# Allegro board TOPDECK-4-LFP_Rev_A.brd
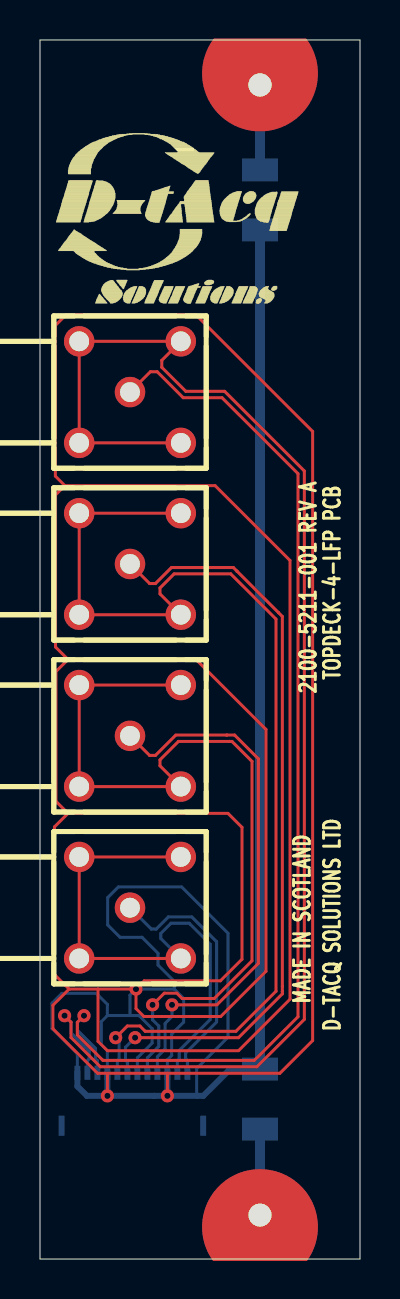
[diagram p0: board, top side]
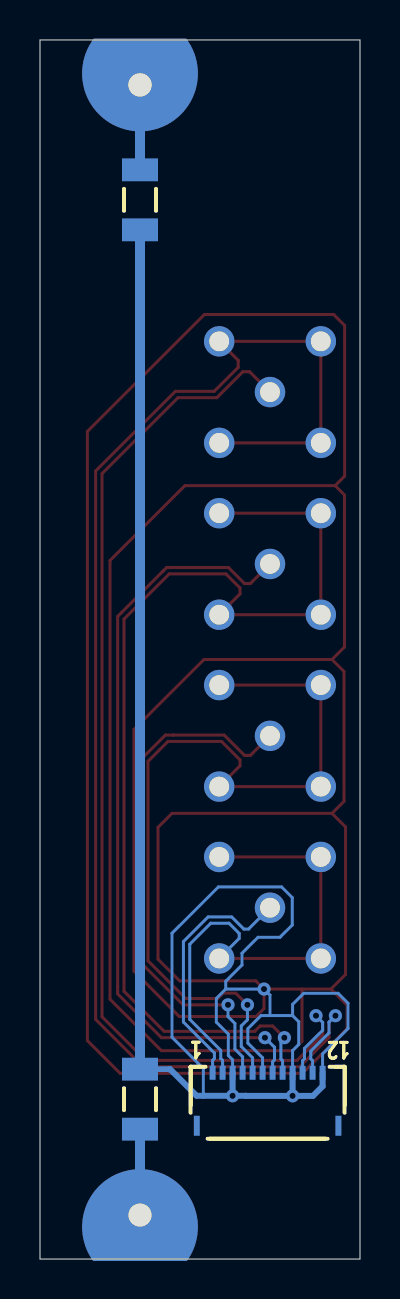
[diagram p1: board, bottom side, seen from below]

Outline 16 x 61 mm; copper layers: TOP, BOTTOM. Coordinates in mm from the lower left corner of the outline.

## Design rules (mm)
net group CHANNEL_5: nets +CHANNEL5 -CHANNEL5
net group CHANNEL_6: nets +CHANNEL6 -CHANNEL6
net group CHANNEL_7: nets +CHANNEL7 -CHANNEL7
net group CHANNEL_8: nets +CHANNEL8 -CHANNEL8
net group POWER: nets 0VA CHASSIS CHASSIS2

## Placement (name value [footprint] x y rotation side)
C1  330PF  [SMC1206]  11 8 90 bottom
C2  330PF  [SMC1206]  11 53 270 bottom
MTG1  CON1  [2_7MM_FIXING_PLATED_5_8MM_PAD]  11 2.2 0 top
MTG2  CON1  [2_7MM_FIXING_PLATED_5_8MM_PAD]  11 58.75 0 top
NOREF  -  []  0 0 90 top
NOREF#2  -  []  0 0 90 top
NOREF#3  -  []  0 0 0 top
NOREF#4  -  []  0 0 0 top
NOREF#5  -  []  0 0 0 top
P1  LEMO_1P_EPL  [LEMO_1P]  4.5 17.58 180 top
P2  LEMO_1P_EPL  [LEMO_1P]  4.5 26.18 180 top
P3  LEMO_1P_EPL  [LEMO_1P]  4.5 34.78 180 top
P4  LEMO_1P_EPL  [LEMO_1P]  4.5 43.38 180 top
P5  503480-1200  [MOLEX_503480-1200]  4.62 9.32 180 bottom

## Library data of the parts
C1 C2 = CAP_NP_1206
MTG1 MTG2 = MOUNT_3_5MM
P1-P4 = LEMO_1P_EPL
P5 = CON12_MOLEX_503480-1200

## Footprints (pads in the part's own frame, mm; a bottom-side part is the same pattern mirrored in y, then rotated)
2_7MM_FIXING_PLATED_5_8MM_PAD
  custom 1.161x1.161 hole 2.692: 1(0,0)
LEMO_1P
  round 1.524 hole 0.991: 1(0,0) 2(-2.54,-2.54) 3(2.54,-2.54) 4(2.54,2.54) 5(-2.54,2.54)
MOLEX_503480-1200
  rect 0.3x0.7 smd: 1(-2.75,0) 2(-2.25,0) 3(-1.75,0) 4(-1.25,0) 5(-0.75,0) 6(-0.25,0) 7(0.25,0) 8(0.75,0) 9(1.25,0) 10(1.75,0) 11(2.25,0) 12(2.75,0)
  rect 0.3x1 smd: 13(-3.54,-2.65) 14(3.54,-2.65)
SMC1206
  rect 1.15x1.8 smd: 1(-1.5,0) 2(1.5,0)

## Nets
0VA: C1.2 C2.2 P5.3 P5.6 P5.9 P5.12
+CHANNEL5: P1.1 P5.1
+CHANNEL6: P2.1 P5.4
+CHANNEL7: P3.1 P5.7
+CHANNEL8: P4.1 P5.10
-CHANNEL5: P1.2 P1.3 P1.4 P1.5 P5.2
-CHANNEL6: P2.2 P2.3 P2.4 P2.5 P5.5
-CHANNEL7: P3.2 P3.3 P3.4 P3.5 P5.8
-CHANNEL8: P4.2 P4.3 P4.4 P4.5 P5.11
CHASSIS: C2.1 MTG2.1
CHASSIS2: C1.1 MTG1.1

Pads without a net: P5 13 14

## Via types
v1: diameter 0.66, hole 0.305, TOP to BOTTOM, 9 vias

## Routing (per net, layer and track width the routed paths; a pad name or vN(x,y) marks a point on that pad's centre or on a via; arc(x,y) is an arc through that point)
0VA: length 306.6
  TOP w0.15: 6.37,9.29 v1(6.37,8.17) ; 6.37,9.29 11.99,9.29 13.63,10.93 13.63,41.41 7.78,47.26 1.32,47.26 0.77,46.72 0.77,39.17 1.24,38.7 ; 6.37,9.29 3.37,9.29 ; 1.24,38.7 0.78,38.23 0.78,30.62 1.4,30 ; 1.24,38.7 8.75,38.7 12.5,34.95 12.5,13 9.93,10.43 3.37,10.43 2.9,10.9 2.9,13.51 ; 1.4,22.3 9.4,22.3 10.1,21.6 10.1,15 9.02,13.92 5.21,13.92 v1(4.8,13.51) ; 1.4,22.3 0.72,21.62 0.72,14.24 1.45,13.51 ; 1.4,22.3 0.8,22.9 0.8,29.4 1.4,30 ; 1.45,13.51 0.65,12.7 0.65,11.52 2.88,9.29 3.37,9.29 ; 1.45,13.51 2.9,13.51 ; 2.9,13.51 v1(4.8,13.51) ; v1(4.8,13.51) 4.8,12.53 5.2,12.14 9.04,12.14 11.3,14.4 11.3,26.5 7.8,30 1.4,30 ; 3.37,9.29 v1(3.37,8.17)
  BOTTOM w0.15: P5.9 3.37,10.43 3.06,10.74 3.06,11.88 3.37,12.18 ; 7.83,8.17 7.83,9.53 9.4,11.1 9.4,16.3 7.08,18.62 3.92,18.62 3.39,18.09 3.39,16.71 4,16.1 5.1,16.1 5.9,15.3 5.9,14.71 6.71,13.9 6.71,13.51 ; 3.37,12.18 3.37,12.74 2.81,13.3 1.1,13.3 0.6,12.8 0.6,11.53 1.87,10.26 P5.12 ; 3.37,12.18 4.5,12.18 ; 4.5,12.18 4.5,13.21 v1(4.8,13.51) 6.71,13.51 ; 4.5,12.18 4.95,12.18 5.61,11.52 5.61,10.81 4.87,10.07 P5.6 ; 6.71,13.51 7.18,13.04 7.18,11.85 6.58,11.25 6.58,10.18 6.37,9.97 P5.3
  BOTTOM w0.3: v1(6.37,8.17) 8.17,8.17 9.5,9.5 C1.2 ; v1(6.37,8.17) P5.3 ; v1(6.37,8.17) 5.71,8.17 5.71,8.17 v1(3.37,8.17) ; P5.9 v1(3.37,8.17) ; v1(3.37,8.17) 2.35,8.17 1.87,8.64 P5.12
  BOTTOM w0.5: C2.2 C1.2
+CHANNEL5: length 12.8
  BOTTOM w0.152: P5.1 7.37,9.94 7.28,10.03 7.28,10.31 8.83,11.86 8.83,15.88 7.59,17.12 6.42,17.12 5.81,16.51 5.57,16.51 P1.1
+CHANNEL6: length 26.9
  TOP w0.152: v1(6.6,12.72) 8.84,12.72 10.92,14.79 10.92,24.77 10.92,25.03 9.73,26.22 9.34,26.22 6.79,26.22 5.77,25.2 5.48,25.2 P2.1
  BOTTOM w0.152: v1(6.6,12.72) 6.6,12.13 6.25,11.79 6.25,10.51 5.87,10.12 P5.4
+CHANNEL7: length 38.5
  TOP w0.152: v1(4.75,11.08) 9.93,11.08 12.12,13.27 12.12,13.39 12.12,13.65 12.12,13.65 12.12,32.15 11.93,32.34 9.67,34.6 6.57,34.6 5.77,33.8 5.48,33.8 P3.1
  BOTTOM w0.152: P5.7 4.37,9.87 4.27,9.96 4.27,10.6 v1(4.75,11.08)
+CHANNEL8: length 55.1
  TOP w0.152: v1(2.2,12.18) 1.87,11.84 1.87,11.22 3.15,9.94 10.72,9.94 12.9,12.12 12.9,39.3 9.1,43.1 7.16,43.1 5.86,44.4 5.52,44.4 P4.1
  BOTTOM w0.152: v1(2.2,12.18) 1.87,11.84 1.87,11.45 2.78,10.54 2.78,10.02 2.87,9.92 P5.10
-CHANNEL5: length 27.1
  TOP w0.152: P1.2 P1.3 P1.4 P1.5
  BOTTOM w0.152: P1.5 6.04,16.04 6.04,16.29 6.55,16.8 7.46,16.8 8.51,15.75 8.51,11.99 6.96,10.44 6.96,10.03 6.87,9.94 P5.2
-CHANNEL6: length 42.2
  TOP w0.152: v1(5.63,12.72) 6.21,13.3 6.84,13.3 7.11,13.04 8.71,13.04 10.6,14.92 10.6,24.9 9.6,25.9 9.47,25.9 6.92,25.9 6,24.98 6,24.68 P2.5 P2.4 P2.3 P2.2
  BOTTOM w0.152: P5.5 5.37,10.07 5.94,10.64 5.94,11.66 5.63,11.97 v1(5.63,12.72)
-CHANNEL7: length 53.7
  TOP w0.152: P3.2 P3.3 P3.4 P3.5 6,33.28 6,33.58 6.71,34.28 9.54,34.28 11.8,32.02 11.8,13.4 9.79,11.39 5.26,11.39 5,11.66 4.37,11.66 v1(3.78,11.08)
  BOTTOM w0.152: P5.8 3.87,9.92 3.96,10.01 3.96,10.9 v1(3.78,11.08)
-CHANNEL8: length 71.5
  TOP w0.152: v1(1.23,12.18) 1.55,11.85 1.55,11.09 3.01,9.62 10.85,9.62 13.22,11.99 13.22,39.43 9.23,43.42 7.29,43.42 6.09,44.62 6.09,44.97 P4.2 P4.3 P4.4 P4.5
  BOTTOM w0.152: P5.11 2.37,9.92 2.46,10.01 2.46,10.4 1.55,11.31 1.55,11.85 v1(1.23,12.18)
CHASSIS: length 4.2
  BOTTOM w0.5: C2.1 MTG2.1
CHASSIS2: length 4.3
  BOTTOM w0.5: C1.1 MTG1.1

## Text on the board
Board Geometry/Soldermask Bottom: 04 | SOLDER RESIST LAYER 2
Ref Des/Silkscreen Bottom: 06 | LEGEND LAYER 2
Board Geometry/Soldermask Top: 03 | SOLDER RESIST LAYER 1
Ref Des/Silkscreen Top: MADE IN SCOTLAND | 2100-5211-001 REV A | TOPDECK-4-LFP PCB | D-TACQ SOLUTIONS LTD | 05 | LEGEND LAYER 1
DIMENSION: 08 | DRILL DRAWING | BOARD TITLE :- TOPDECK-4-LFP PCB 2100-5211-001 REV A | BOARD MATERIAL :- DOUBLE-SIDED, 1.6mm THK, FR4, 1oz FINISHED | SOLDER RESIST:- ON BOTH SIDES, GREEN PHOTOIMAGEABLE, S.M.O.B.C., H.A.S.L. | SOLDER RESIST SWELL IS SIZE FOR SIZE, MANUFACTURER TO ADJUST SWELL TO | PREVENT INK ON PADS AND EXPOSED COPPER | SILKSCREEN:- WHITE ON BOTH LAYERS | GENERAL HOLE TOLERANCE:- +0.1/-0.05 | LINEAR TOLERANCE 2 DEC PLACES +/- 0.1 | LINEAR TOLERANCE 1 DEC PLACE +/- 0.2 | REMOVE ALL BURRS AND SHARP EDGES | MANUFACTURER'S LOGO, DATECODE AND APPROVAL STATUS (WHERE APPLICABLE), TO BE | INDELIBLY MARKED ON THE SILKSCREEN | IF NO SILKSCREEN IS USED, LOGO TO BE ADDED APPROXIMATELY IN THE AREA SHOWN | ALL DIMENSIONS IN mm | FIGURE | SIZE | 0.30 | 0.99 | 2.69 | FINISHED HOLE SIZE: TOP to BOTTOM | ALL UNITS ARE IN MILLIMETERS | PLATED | QTY | 9 | 20 | 2
BODY_CENTER: 01 | LAYER 1
DISPLAY_BOTTOM: 02 | LAYER 2
PLACE_BOUND_BOTTOM: 10 | ASSEMBLY DRAWING LAYER 1
DEVICE_TYPE_BOTTOM: 11 | ASSEMBLY DRAWING LAYER 2
User.6: 07 | SOLDER PASTE MASK LAYER 1
User.7: 07 | SOLDER PASTE MASK LAYER 2
User.8: GOLD MASK LAYER 1
User.9: GOLD MASK LAYER 2
User.10: CARBON MASK LAYER 1
User.11: CARBON MASK LAYER 2
User.12: TEST POINT DRAWING LAYER 1
User.13: TEST POINT DRAWING LAYER 2
User.14: Tel: 01835 826390 | Fax: 01835 826391 | E-mail: info@intrasysdesign.com | Web: www.intrasysdesign.com | Job No: | Date: | Description: | Sheet | of | 08 | 3202 | MAY 15
User.15: D-TACQ SOLUTIONS LTD | 2100-5211-001 REV A | ASSEMBLY DRAWING TOP
User.17: D-TACQ SOLUTIONS LTD | 2100-5211-001 REV A | ASSEMBLY DRAWING BOTTOM
